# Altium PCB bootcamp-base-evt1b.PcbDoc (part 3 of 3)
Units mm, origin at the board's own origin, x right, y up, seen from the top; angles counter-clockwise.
Board outline 49.31 x 77.41 mm, 4 copper layers (Top Layer, Internal Plane 1, Internal Plane 2, Bottom Layer), stack 1.597 mm thick; 178 components, 122 nets, 1398 pads, 353 vias.
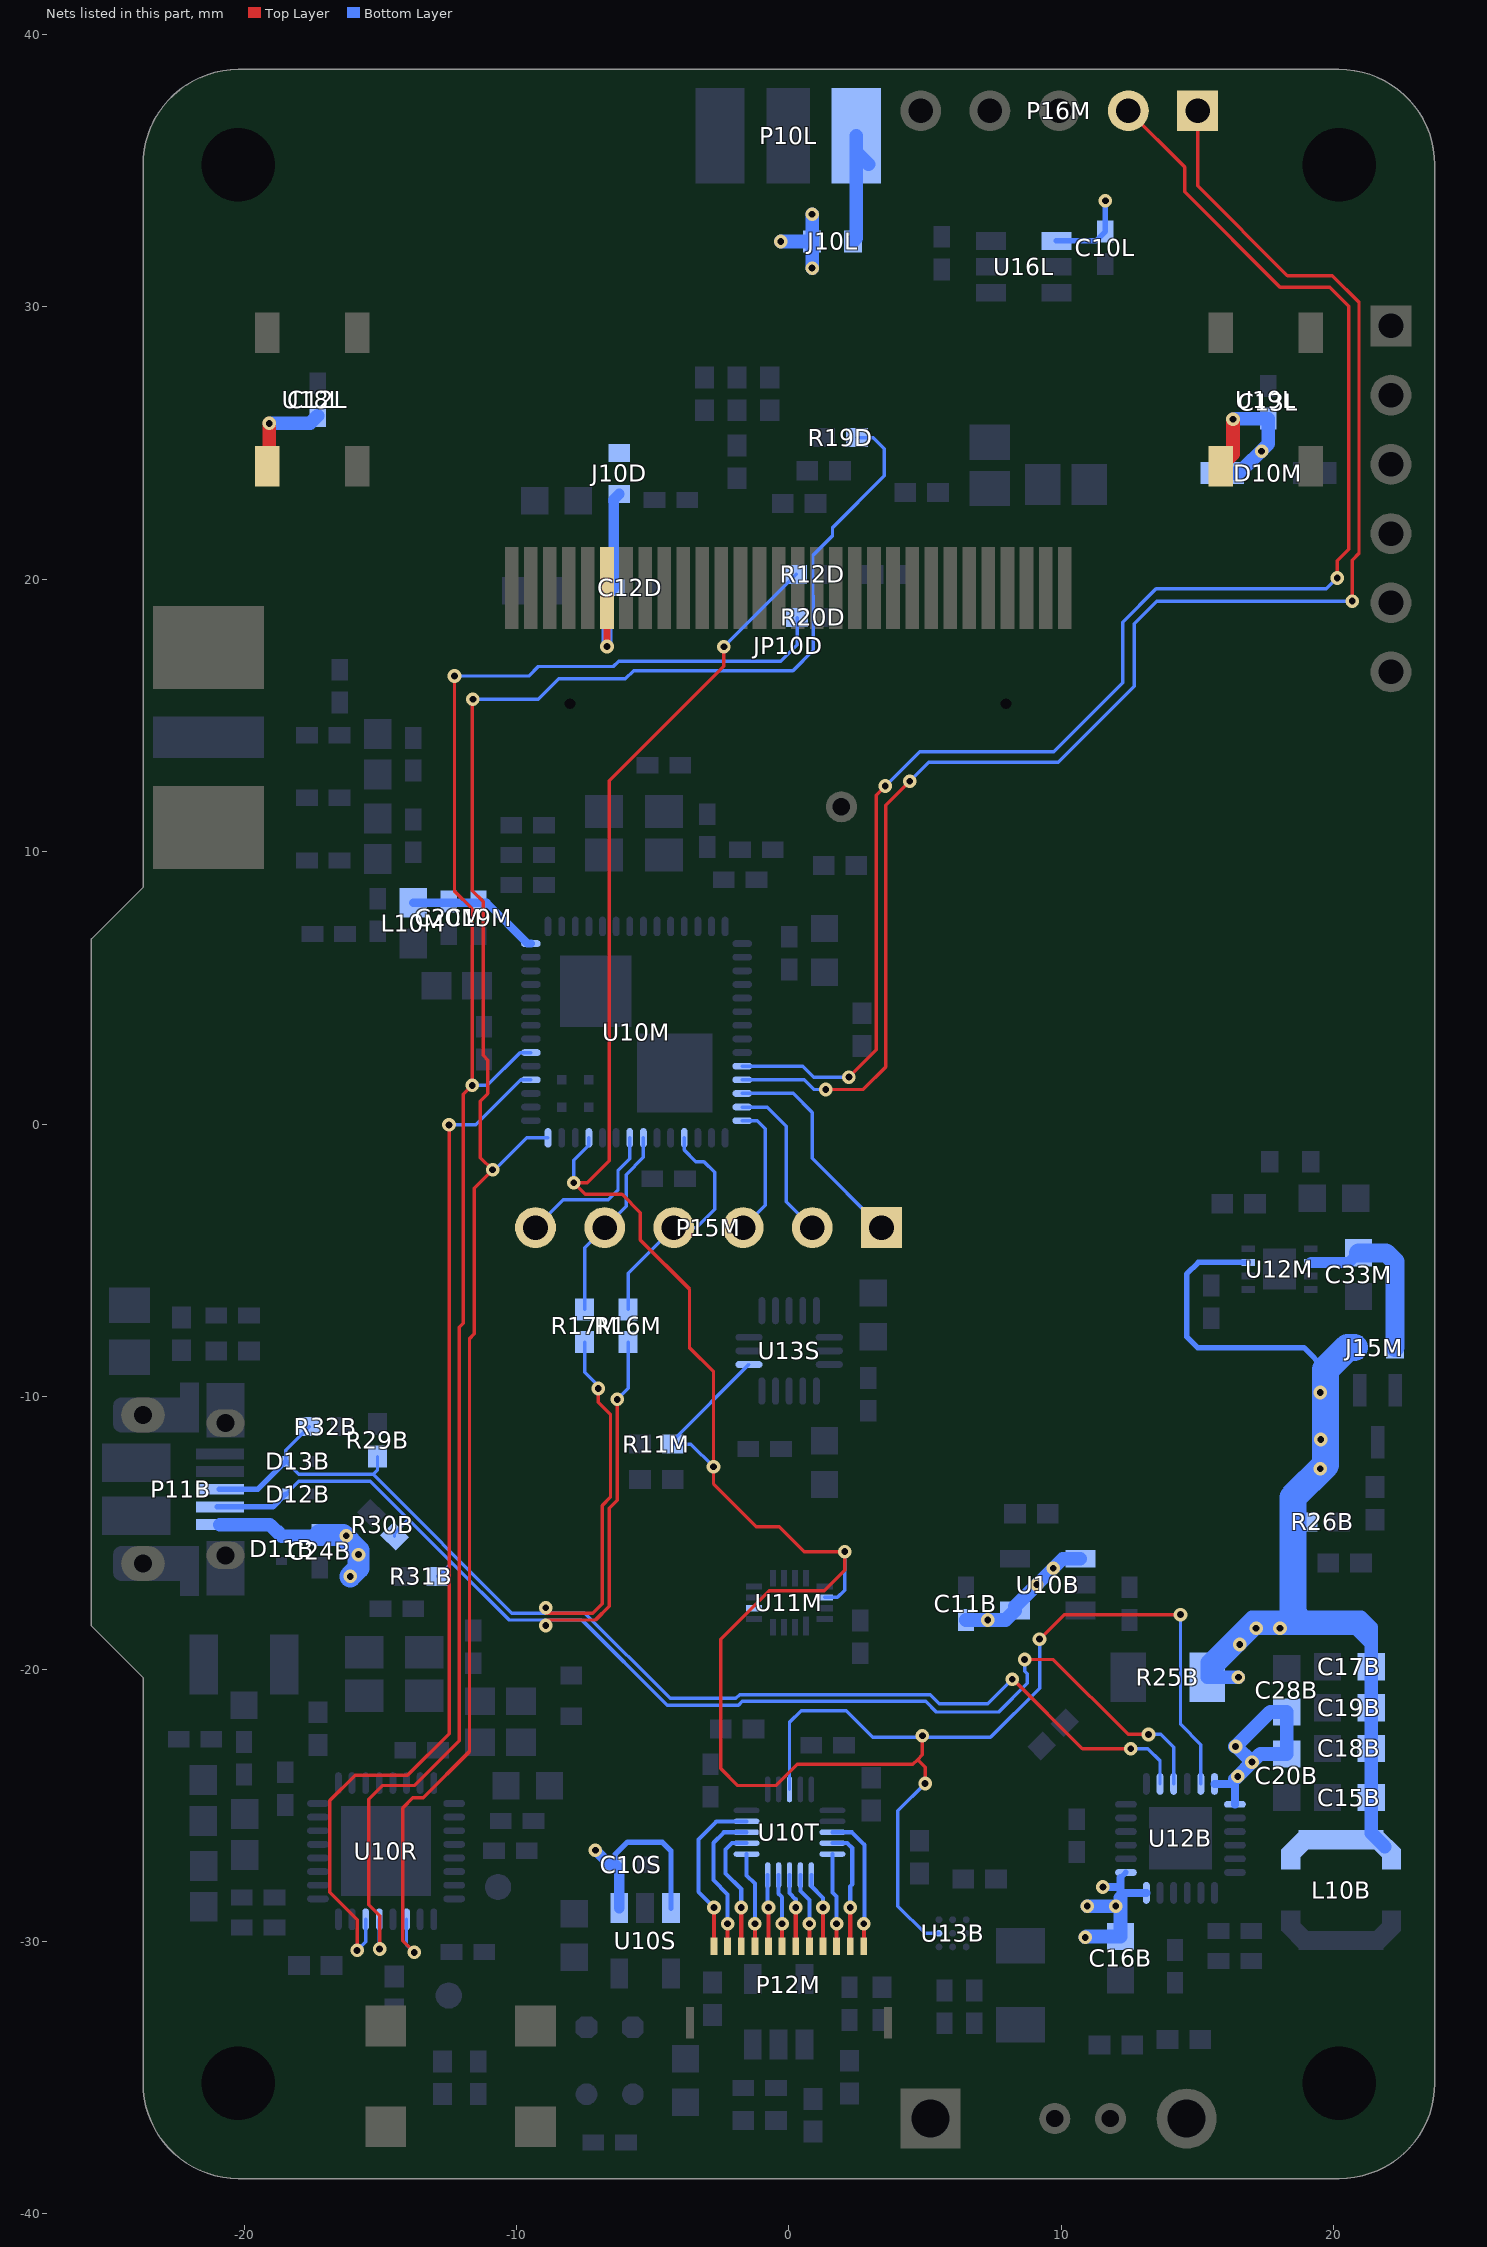
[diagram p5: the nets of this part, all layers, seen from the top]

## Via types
v1: diameter 0.5, hole 0.25, Top Layer to Bottom Layer, tented both sides, 320 vias
v2: diameter 0.5, hole 0.2, Top Layer to Bottom Layer, 18 vias
v3: diameter 0.66, hole 0.33, Top Layer to Bottom Layer, tented top, 13 vias
v4: diameter 0.5, hole 0.2, Top Layer to Bottom Layer, tented top, 2 vias

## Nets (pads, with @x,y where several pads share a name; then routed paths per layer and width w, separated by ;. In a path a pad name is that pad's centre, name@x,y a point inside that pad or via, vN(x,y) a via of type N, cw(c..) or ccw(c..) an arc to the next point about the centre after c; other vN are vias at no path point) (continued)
SDA: R11M.1 R12D.2 U10M.25 U10T.3 U11M.14 U12B.17 U13B.A2 U13S.6 | length 110.4
  Top Layer w0.125: v1(-2.388,17.525) -2.388,16.812 -6.6,12.6 -6.6,-1.35 -7.4,-2.15 v1(-7.9,-2.15) -7.475,-2.575 -6.125,-2.575 -5.45,-3.25 -5.45,-4.25 -3.65,-6.05 -3.65,-8.2 -2.767,-9.083 v1(-2.767,-12.571) -2.767,-13.208 -1.2,-14.775 -0.35,-14.775 0.563,-15.688 v1(2.05,-15.688) 2.05,-16.375 1.3,-17.125 -0.725,-17.125 -2.5,-18.9 -2.5,-23.65 -1.875,-24.275 -0.475,-24.275 0.3,-23.5 4.55,-23.5 4.725,-23.325 ; v1(4.9,-22.45) 4.9,-23.15 4.725,-23.325 ; v1(5,-24.2) 5,-23.6 4.725,-23.325 ; v1(9.2,-18.9) 10.1,-18 v1(14.375,-18)
  Bottom Layer w0.125: v1(-7.9,-2.15) -7.9,-1.325 -7.342,-0.767 U10M.25@-7.342,-0.501 ; v1(-2.767,-12.571) -3.597,-11.741 R11M.1@-4.263,-11.741 -4.263,-11.617 U13S.6@-1.467,-8.821 ; v1(-2.388,17.525) R12D.2@0.272,20.184 ; U10T.3@0.022,-24.416 0.022,-21.953 0.45,-21.525 2.1,-21.525 3.075,-22.5 7.4,-22.5 9.2,-20.7 v1(9.2,-18.9) ; U11M.14@1.321,-17.367 1.783,-17.367 2.05,-17.1 v1(2.05,-15.688) ; v1(5,-24.2) 4,-25.2 4,-28.7 5,-29.7 U13B.A2@5.508,-29.7 ; v1(14.375,-18) 14.375,-22.025 15.122,-22.772 U12B.17@15.122,-24.216
SPI1_MISO: U10M.32 U10R.14 | length 38.6
  Top Layer w0.125: v1(-15.85,-30.325) -15.85,-29.2 -16.85,-28.2 -16.85,-24.825 -15.925,-23.9 -14,-23.9 -12.475,-22.375 v1(-12.475,-0.025)
  Bottom Layer w0.125: v1(-15.85,-30.325) -15.536,-30.011 U10R.14@-15.536,-29.184 ; v1(-12.475,-0.025) -11.5,-0.025 -9.846,1.629 U10M.32@-9.472,1.629
SPI1_MOSI: R20D.2 U10M.34 U10R.13 | length 67.2
  Top Layer w0.125: v1(-15.025,-30.275) -15.025,-29.05 -15.425,-28.65 -15.425,-24.775 -14.925,-24.275 -13.75,-24.275 -12.1,-22.625 -12.1,-7.45 -11.95,-7.3 -11.95,1.1 v1(-11.625,1.425) -11.625,7.9 -12.275,8.55 v1(-12.275,16.45)
  Bottom Layer w0.125: U10R.13@-15.036,-29.184 -15.036,-30.264 v1(-15.025,-30.275) ; v1(-12.275,16.45) -9.55,16.45 -9.2,16.8 -6.45,16.8 -6.25,17 -0.3,17 0.3,17.6 R20D.2@0.3,18.6 ; v1(-11.625,1.425) -11.075,1.425 -9.871,2.629 U10M.34@-9.472,2.629
SPI1_SCK: R19D.2 U10M.28 U10R.11 | length 75.1
  Top Layer w0.125: v1(-13.75,-30.4) -14.175,-29.975 -14.175,-25.1 -13.8,-24.725 -13.425,-24.725 -11.725,-23.025 -11.725,-7.875 -11.55,-7.7 -11.55,-2.35 v1(-10.875,-1.675) -11.325,-1.225 -11.325,0.85 -11.05,1.125 -11.05,2.35 -11.225,2.525 -11.225,8.175 -11.625,8.575 -11.625,15.575 v1(-11.6,15.6)
  Bottom Layer w0.125: U10R.11@-14.036,-29.184 -14.036,-30.114 v1(-13.75,-30.4) ; v1(-11.6,15.6) -9.2,15.6 -8.45,16.35 -6,16.35 -5.7,16.65 0.15,16.65 0.9,17.4 0.9,19.4 0.884,19.416 0.884,20.884 1.6,21.6 1.6,21.9 3.5,23.8 3.5,24.8 3.1,25.2 R19D.2@2.5,25.2 ; v1(-10.875,-1.675) -10.8,-1.675 -9.626,-0.501 U10M.28@-8.842,-0.501
SWD_CLK_TOUCH1: P16M.2 U10M.10 | length 58.1
  Top Layer w0.125: v1(2.2,1.729) 3.2,2.729 3.2,12.075 v1(3.538,12.412) ; P16M.2@12.46,37.2 14.525,35.135 14.525,34.225 18.025,30.725 19.85,30.725 20.55,30.025 20.55,21.105 20.125,20.68 v1(20.125,20.05)
  Bottom Layer w0.125: U10M.10@-1.712,2.129 0.508,2.129 0.908,1.729 v1(2.2,1.729) ; v1(3.538,12.412) 4.8,13.675 9.725,13.675 12.25,16.2 12.25,18.425 13.475,19.65 19.725,19.65 v1(20.125,20.05)
SWD_DIO_TOUCH4: P16M.1 U10M.11 | length 58.5
  Top Layer w0.125: v1(1.35,1.275) 2.725,1.275 3.55,2.1 3.55,11.7 v1(4.438,12.588) ; P16M.1@15,37.2 15,34.45 18.3,31.15 19.95,31.15 20.925,30.175 20.925,20.95 20.675,20.7 v1(20.675,19.2)
  Bottom Layer w0.125: U10M.11@-1.712,1.629 0.558,1.629 0.912,1.275 v1(1.35,1.275) ; v1(4.438,12.588) 5.136,13.286 9.886,13.286 12.675,16.075 12.675,18.375 13.5,19.2 v1(20.675,19.2)
TOUCH2: P15M.3 U10M.14 | length 4.9
  Bottom Layer w0.125: U10M.14@-1.712,0.129 -1.167,0.129 -0.867,-0.171 -0.867,-2.981 P15M.3@-1.682,-3.796
TOUCH3: P15M.2 U10M.13 | length 6
  Bottom Layer w0.125: U10M.13@-1.712,0.629 -0.792,0.629 -0.092,-0.071 -0.092,-2.846 P15M.2@0.858,-3.796
TOUCH5: P15M.1 U10M.12 | length 8.1
  Bottom Layer w0.125: U10M.12@-1.712,1.129 0.158,1.129 0.858,0.429 0.858,-1.256 P15M.1@3.398,-3.796
TOUCH6: P15M.4 R16M.2 U10M.18 | length 8.7
  Bottom Layer w0.125: R16M.2@-5.9,-6.8 -5.9,-5.475 P15M.4@-4.222,-3.796 -3.396,-3.796 -2.725,-3.125 -2.725,-1.763 -3.117,-1.371 -3.417,-1.371 -3.842,-0.946 U10M.18@-3.842,-0.501
TOUCH7: P15M.5 R17M.2 U10M.21 | length 7.2
  Bottom Layer w0.125: R17M.2@-7.5,-6.8 -7.5,-4.535 P15M.5@-6.762,-3.796 -5.975,-3.01 -5.975,-1.855 -5.342,-1.221 U10M.21@-5.342,-0.501
TOUCH8: P15M.6 U10M.22 | length 5.7
  Bottom Layer w0.125: P15M.6@-9.302,-3.796 -8.28,-2.775 -6.625,-2.775 -6.275,-2.425 -6.275,-1.705 -5.842,-1.271 U10M.22@-5.842,-0.501
TPAD0: P12M.1 U10T.19 | length 6.2
  Top Layer w0.15: P12M.1@-2.75,-30.175 v1(-2.75,-28.75)
  Bottom Layer w0.15: v1(-2.75,-28.75) -3.325,-28.175 -3.325,-26.25 -2.666,-25.591 U10T.19@-1.553,-25.591
TPAD1: P12M.2 U10T.18 | length 5.4
  Top Layer w0.15: P12M.2@-2.25,-30.175 v1(-2.25,-29.35)
  Bottom Layer w0.15: v1(-2.25,-29.35) -2.25,-28.275 -2.775,-27.75 -2.775,-26.375 -2.391,-25.991 U10T.18@-1.553,-25.991
TPAD2: P12M.3 U10T.17 | length 4.7
  Top Layer w0.15: P12M.3@-1.75,-30.175 v1(-1.75,-28.75)
  Bottom Layer w0.15: v1(-1.75,-28.75) -1.75,-28.075 -2.325,-27.5 -2.325,-26.625 -2.091,-26.391 U10T.17@-1.553,-26.391
TPAD3: P12M.4 U10T.16 | length 3.5
  Top Layer w0.15: P12M.4@-1.25,-30.175 v1(-1.25,-29.35)
  Bottom Layer w0.15: U10T.16@-1.553,-26.791 -1.553,-27.572 -1.25,-27.875 v1(-1.25,-29.35)
TPAD4: P12M.5 U10T.15 | length 2.6
  Top Layer w0.15: P12M.5@-0.75,-30.175 v1(-0.75,-28.75)
  Bottom Layer w0.15: U10T.15@-0.778,-27.566 -0.778,-28.722 v1(-0.75,-28.75)
TPAD5: P12M.6 U10T.14 | length 2.7
  Top Layer w0.15: P12M.6@-0.25,-30.175 v1(-0.25,-29.35)
  Bottom Layer w0.15: U10T.14@-0.378,-27.566 -0.378,-28.247 -0.25,-28.375 v1(-0.25,-29.35)
TPAD6: P12M.7 U10T.13 | length 2.7
  Top Layer w0.15: P12M.7@0.25,-30.175 v1(0.25,-28.75)
  Bottom Layer w0.15: U10T.13@0.022,-27.566 0.022,-28.222 0.25,-28.45 v1(0.25,-28.75)
TPAD7: P12M.8 U10T.12 | length 2.7
  Top Layer w0.15: P12M.8@0.75,-30.175 v1(0.75,-29.35)
  Bottom Layer w0.15: U10T.12@0.422,-27.566 0.422,-28.147 0.75,-28.475 v1(0.75,-29.35)
TPAD8: P12M.9 U10T.11 | length 2.8
  Top Layer w0.15: P12M.9@1.25,-30.175 v1(1.25,-28.75)
  Bottom Layer w0.15: U10T.11@0.822,-27.566 0.822,-27.972 1.25,-28.4 v1(1.25,-28.75)
TPADA: P12M.12 U10T.8 | length 5.1
  Top Layer w0.15: P12M.12@2.75,-30.175 v1(2.75,-29.35)
  Bottom Layer w0.15: U10T.8@1.597,-25.991 2.316,-25.991 2.775,-26.45 2.775,-29.325 v1(2.75,-29.35)
TPADB: P12M.11 U10T.9 | length 4.4
  Top Layer w0.15: P12M.11@2.25,-30.175 v1(2.25,-28.75)
  Bottom Layer w0.15: U10T.9@1.597,-26.391 2.141,-26.391 2.325,-26.575 2.325,-27.9 2.25,-27.975 v1(2.25,-28.75)
TPADC: P12M.10 U10T.10 | length 3.4
  Top Layer w0.15: P12M.10@1.75,-30.175 v1(1.75,-29.35)
  Bottom Layer w0.15: U10T.10@1.597,-26.791 1.597,-28.197 1.75,-28.35 v1(1.75,-29.35)
USBD_N: D12B.1 P11B.2 R16M.1 R30B.1 R31B.1 U12B.15 | length 57.3
  Top Layer w0.125: v1@-8.9,-18.2 -7.1,-18.2 -6.6,-17.7 -6.6,-14.1 -6.3,-13.8 v1(-6.3,-10.1) ; v1(8.65,-19.65) 9.7,-19.65 12.45,-22.4 v1(13.2,-22.4)
  Bottom Layer w0.125: D12B.1@-18.473,-13.579 -17.998,-13.104 -15.366,-13.104 -13.97,-14.5 ; R30B.1@-14.476,-15.124 -14.476,-15.006 -13.97,-14.5 ; R31B.1@-12.9,-16.6 -12.87,-16.6 -12.37,-16.1 ; v1(-6.3,-10.1) -5.9,-9.7 R16M.1@-5.9,-8 ; v1(8.65,-19.65) 8.65,-20.075 8.75,-20.175 8.75,-20.525 7.7,-21.575 5.414,-21.575 5.025,-21.186 -1.707,-21.186 -1.85,-21.329 -4.466,-21.329 -7.595,-18.2 -10.27,-18.2 -12.37,-16.1 ; v1(13.2,-22.4) 13.65,-22.4 14.122,-22.872 U12B.15@14.122,-24.216 ; -13.97,-14.5 -12.37,-16.1
  Bottom Layer w0.2: P11B.2@-20.989,-14.044 -18.938,-14.044 D12B.1@-18.473,-13.579
  other v1: -8.925,-18.4
USBD_P: D13B.1 P11B.3 R17M.1 R29B.1 R32B.1 U12B.14 | length 55.9
  Top Layer w0.125: v1@-8.9,-17.95 -7.204,-17.95 -6.85,-17.596 -6.85,-13.996 -6.55,-13.696 -6.55,-10.65 -7,-10.2 v1(-7,-9.7) ; v1(8.2,-20.375) 8.225,-20.375 10.775,-22.925 v1(12.55,-22.925)
  Bottom Layer w0.125: R32B.1@-17.6,-11.1 -18.473,-11.973 D13B.1@-18.473,-12.379 -17.998,-12.854 -15.263,-12.854 ; R29B.1@-15.1,-12.2 -15.1,-12.691 -15.263,-12.854 ; R17M.1@-7.5,-8 -7.5,-9.1 -7,-9.6 v1(-7,-9.7) ; v1(8.2,-20.375) 7.3,-21.275 5.525,-21.275 5.186,-20.936 -1.811,-20.936 -1.954,-21.079 -4.363,-21.079 -7.492,-17.95 -10.167,-17.95 -15.263,-12.854 ; v1(12.55,-22.925) 13.175,-22.925 13.622,-23.372 U12B.14@13.622,-24.216
  Bottom Layer w0.2: P11B.3@-20.916,-13.398 -19.492,-13.398 D13B.1@-18.473,-12.379
  other v1: -8.925,-17.75
USBOUT_EN_N: U11M.6
VBAT_SYS: C10S.1 C12D.1 C15B.1 C16B.1 C17B.1 C18B.1 C19B.1 C33M.1 J10D.1 J15M.1 JP10D.6 L10B.2 R25B.2 R26B.2 U10S.1 U10S.3 U12B.6 U12B.7 U12M.2 U12M.7 | length 73.7
  Top Layer w0.25: v1(-6.678,17.534) JP10D.6@-6.678,19.684
  Bottom Layer w0.2: C10S.1@-6.379,-27.177 -6.379,-26.804 -5.925,-26.35 -4.65,-26.35 -4.329,-26.671 U10S.3@-4.329,-28.777 ; 12.172,-28.391 12.347,-28.216 ; 12.172,-27.666 U12B.7@12.372,-27.466 ; U12M.7@16.858,-5.071 15.029,-5.071 14.6,-5.5 14.6,-7.8 15,-8.2 18.9,-8.2 19.7,-9
  Bottom Layer w0.3: v1(11.525,-28) 12.172,-28 ; 12.172,-28.391 12.172,-28 ; 12.172,-27.666 12.172,-28 ; 12.347,-28.216 U12B.6@13.122,-28.216
  Bottom Layer w0.4: v1(-7.104,-26.652) -6.579,-27.177 C10S.1@-6.379,-27.177 -6.229,-27.327 U10S.1@-6.229,-28.777 ; v1(-6.678,17.534) -6.678,19.434 C12D.1@-6.428,19.684 -6.428,22.934 J10D.1@-6.228,23.134 ; U12M.2@19.158,-5.071 20.558,-5.071 C33M.1@20.908,-4.721
  Bottom Layer w0.5: v1(10.875,-29.85) 10.909,-29.816 C16B.1@12.172,-29.816 v1@12.172,-28.7 ; v1(10.95,-28.7) v1@12.172,-28.7 ; 12.172,-28.391 v1@12.172,-28.7 ; v1(16.5,-20.3) R25B.2@15.35,-20.3 ; L10B.2@21.872,-26.516 21.372,-26.016 C15B.1@21.372,-24.716 C18B.1@21.372,-22.916 C19B.1@21.372,-21.416 C17B.1@21.372,-19.916 21.372,-19.066 ; R25B.2@15.35,-20.3 15.35,-19.75 17,-18.1 18.6,-18.1 21,-18.1 21.372,-18.472 21.372,-19.066 ; R25B.2@15.35,-20.3 v1(17.15,-18.5) v1(18.025,-18.5) 20.806,-18.5 21.372,-19.066
  Bottom Layer w0.7: C33M.1@20.908,-4.721 21.921,-4.721 22.25,-5.05 J15M.1@22.25,-8.2
  Bottom Layer w1: 18.6,-18.1 18.5,-18 18.5,-13.7 19.7,-12.5 19.7,-9 20.5,-8.2 J15M.1@20.75,-8.2
  other v1: 12,-28.7 16.55,-19.1 19.5,-12.65 19.525,-11.575 19.5,-9.85
VR_PA: C19M.1 C20M.1 L10M.1 U10M.42 | length 4.9
  Bottom Layer w0.3: L10M.1@-13.792,8.129 -11.092,8.129 -9.592,6.629 U10M.42@-9.472,6.629
VUSB: C10L.1 C11B.1 C12L.1 C13L.1 C20B.1 C24B.1 C28B.1 D10M.2 D11B.1 J10L.1 P10L.3 P11B.1 U10B.1 U10B.4 U12B.18 U12B.19 U16L.1 U18L.1 U19L.1 | length 41.4
  Top Layer w0.5: U18L.1@-19.15,24.15 -19.075,24.225 v1(-19.075,25.725) ; U19L.1@15.85,24.15 16.3,24.6 v1(16.3,25.875)
  Bottom Layer w0.2: U16L.1@9.816,32.422 11.266,32.422 C10L.1@11.616,32.772 v1(11.616,33.897) ; 16.197,-24.216 v1@16.372,-24.041
  Bottom Layer w0.3: U12B.18@15.622,-24.216 16.197,-24.216 ; U12B.19@16.372,-24.966 v1@16.372,-24.041
  Bottom Layer w0.5: P11B.1@-20.882,-14.7 -19.051,-14.7 D11B.1@-18.623,-15.129 ; v1(-19.075,25.725) -17.575,25.725 C12L.1@-17.3,26 ; -18.748,-14.954 D11B.1@-18.623,-15.129 ; C24B.1@-17.223,-15.079 -17.273,-15.129 D11B.1@-18.623,-15.129 ; v1(-0.3,32.4) J10L.1@0.85,32.4 ; v1(0.85,31.425) J10L.1@0.85,32.4 ; v1(0.85,33.4) J10L.1@0.85,32.4 ; J10L.1@2.35,32.4 2.472,32.522 P10L.3@2.472,35.684 ; P10L.3@2.472,36.284 P10L.3@2.472,35.684 ; P10L.3@2.922,35.234 P10L.3@2.472,35.684 ; C11B.1@6.5,-18.2 7.95,-18.2 U10B.4@8.3,-17.85 8.3,-17.7 10.05,-15.95 U10B.1@10.7,-15.95 ; D10M.2@15.9,23.9 16.525,23.9 17.6,24.975 C13L.1@17.6,25.9 16.325,25.9 v1(16.3,25.875) ; v1@16.372,-24.041 v1(16.472,-23.941) v1(16.997,-23.416) ; v1@16.372,-22.841 v1(16.397,-22.841) ; v1(16.397,-22.841) 16.422,-22.841 v1(16.997,-23.416) ; v1(16.397,-22.841) 17.662,-21.575 C28B.1@18.275,-21.575 18.272,-21.578 C20B.1@18.272,-23.116 17.297,-23.116 v1(16.997,-23.416)
  Bottom Layer w0.8: C24B.1@-17.223,-15.079 -16.367,-15.079 -15.8,-15.645 -15.8,-16.3 v1(-16.1,-16.6)
  other v1: 7.3,-18.2 9.1,-16.9 9.7,-16.3 -15.8,-15.8 -16.248,-15.104 17.35,24.7
pads on no net: JP10D.0 JP10D.7 P11B.4 P11M.2 P11M.6 P12M.0 U10M.30 U10M.37 U10M.41 U10M.50 U10M.51 U10M.52 U10M.53 U10M.57 U10M.58 U10M.59 U10M.60 U10R.4 U10R.5 U10R.6 U10R.15 U10S.4 U12B.11 U12M.5 U13S.3 U13S.8 U13S.9 U13S.13 U13S.15 U13S.16

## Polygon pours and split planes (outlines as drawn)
GND on Bottom Layer "bot-gnd" (solid, remove dead copper, pour order 6): -31.5,-42.65 25.95,-42.65 29.325,-39.275 29.325,37.175 24.45,42.05 -25.225,42.05 -29.8,37.475 -30.4,36.875 -30.4,-42.875
GND on Top Layer "top-gnd" (solid, remove dead copper, pour order 4): -32,-40.9 23.475,-40.9 29.175,-35.2 29.175,37.9 25.025,42.05 -27.95,42.05 -33.7,36.3 -33.7,-39.15 -31.95,-40.9
VBAT_SYS on Internal Plane 1 (split plane): 170 vertices, not listed, extent -7.473,-32.898 20.398,23.556
VUSB on Internal Plane 1 (split plane): 234 vertices, not listed, extent -25.09,-38.192 23.198,38.206
P3.0V on Internal Plane 1 (split plane): 10.028,30.728 10.061,30.706 10.1,30.698 11.758,30.698 13.398,29.058 13.398,24.5 13.406,24.461 13.428,24.428 14.156,23.7 10.858,20.402 -5.8,20.402 -5.839,20.394 -5.872,20.372 -7.572,18.672 -7.594,18.639 -7.602,18.6 -7.602,17 -7.594,16.961 -7.572,16.928 -7.272,16.628 -7.239,16.606 -7.2,16.598 -6.4,16.598 -6.361,16.606 -6.328,16.628 -4.158,18.798 11.4,18.798 11.439,18.806 11.472,18.828 13.442,20.798 16.033,20.798 18.098,18.733 18.098,-2.4 18.106,-2.439 18.128,-2.472 18.598,-2.942 18.598,-7.758 17.828,-8.528 17.806,-8.561 17.798,-8.6 17.798,-11.958 16.158,-13.598 13.542,-13.598 12.372,-12.428 12.339,-12.406 12.3,-12.398 6.1,-12.398 6.061,-12.406 6.028,-12.428 3.728,-14.728 3.706,-14.761 3.698,-14.8 3.698,-20.5 3.706,-20.539 3.728,-20.572 5.528,-22.372 5.561,-22.394 5.6,-22.402 8,-22.402 8.039,-22.394 8.072,-22.372 9.942,-20.502 10.258,-20.502 10.598,-20.842 10.598,-23.358 9.658,-24.298 9.1,-24.298 9.061,-24.306 9.028,-24.328 6.728,-26.628 4.528,-28.828 2.558,-30.798 -2.333,-30.798 -3.398,-29.733 -3.398,-28.325 -3.406,-28.286 -3.428,-28.253 -3.753,-27.928 -3.786,-27.906 -3.825,-27.898 -4.358,-27.898 -6.328,-25.928 -6.361,-25.906 -6.4,-25.898 -7.175,-25.898 -7.214,-25.906 -7.247,-25.928 -7.647,-26.328 -7.669,-26.361 -7.677,-26.4 -7.677,-27 -7.669,-27.039 -7.647,-27.072 -7.102,-27.617 -7.102,-31.798 -16.858,-31.798 -19.898,-28.758 -19.898,-27.842 -19.428,-27.372 -19.406,-27.339 -19.398,-27.3 -19.398,-20.442 -16.458,-17.502 -15.8,-17.502 -15.761,-17.494 -15.728,-17.472 -15.028,-16.772 -15.006,-16.739 -14.998,-16.7 -14.998,-15.4 -15.006,-15.361 -15.028,-15.328 -16.003,-14.353 -16.036,-14.331 -16.075,-14.323 -25.09,-14.323 -25.09,6.589 -23.346,8.332 -23.283,8.409 -23.236,8.498 -23.206,8.593 -23.197,8.693 -23.197,22.498 -15,22.498 -14.961,22.506 -14.928,22.528 -14.128,23.328 -14.106,23.361 -14.098,23.4 -14.098,29.658 -13.008,30.748 1.85,30.748 1.889,30.756 1.922,30.778 4.342,33.198 7.558,33.198
GND on Internal Plane 2 (split plane): 20.442,38.197 20.675,38.169 20.906,38.123 21.132,38.06 21.352,37.978 21.565,37.88 21.77,37.765 21.966,37.635 22.15,37.489 22.323,37.33 22.482,37.157 22.628,36.973 22.758,36.778 22.873,36.573 22.971,36.359 23.053,36.139 23.116,35.913 23.162,35.682 23.19,35.449 23.198,35.23 23.197,35.214 23.197,-35.186 23.197,-35.187 23.197,-35.201 23.198,-35.217 23.19,-35.435 23.162,-35.668 23.116,-35.898 23.053,-36.125 22.971,-36.345 22.873,-36.558 22.758,-36.763 22.628,-36.959 22.482,-37.143 22.323,-37.316 22.15,-37.475 21.966,-37.621 21.77,-37.751 21.565,-37.866 21.352,-37.964 21.132,-38.046 20.906,-38.109 20.675,-38.155 20.442,-38.183 20.214,-38.192 20.194,-38.19 -20.207,-38.19 -20.223,-38.191 -20.442,-38.183 -20.675,-38.155 -20.906,-38.109 -21.132,-38.045 -21.352,-37.964 -21.565,-37.866 -21.77,-37.751 -21.966,-37.621 -22.15,-37.475 -22.323,-37.316 -22.482,-37.143 -22.628,-36.959 -22.758,-36.763 -22.873,-36.558 -22.971,-36.345 -23.053,-36.125 -23.116,-35.898 -23.162,-35.668 -23.19,-35.435 -23.198,-35.217 -23.197,-35.2 -23.197,-20.31 -23.206,-20.21 -23.236,-20.115 -23.283,-20.026 -23.346,-19.949 -25.09,-18.206 -25.09,6.589 -23.346,8.332 -23.283,8.409 -23.236,8.498 -23.206,8.593 -23.197,8.693 -23.197,35.2 -23.199,35.22 -23.19,35.449 -23.162,35.682 -23.116,35.913 -23.052,36.139 -22.971,36.359 -22.873,36.572 -22.758,36.777 -22.628,36.973 -22.482,37.157 -22.323,37.33 -22.15,37.489 -21.966,37.635 -21.77,37.765 -21.565,37.88 -21.352,37.978 -21.132,38.06 -20.906,38.123 -20.675,38.169 -20.442,38.197 -20.223,38.205 -20.207,38.204 20.179,38.204 20.199,38.206 20.207,38.206

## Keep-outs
Keep-Out Layer:
  lines w0.2: -23.707,8.693 -23.707,22.3
  lines w0.5: -25.6,-18.417 -25.6,6.8 -23.707,8.693
  lines w1: -25.6,-18.417 -23.707,-20.31 -23.707,-35.2 ccw(c-20.207,-35.2) -20.207,-38.7 20.194,-38.7 ccw(c20.207,-35.2) 23.707,-35.2 ; -23.707,22.3 -23.707,35.2 cw(c-20.207,35.214) -20.207,38.714 20.179,38.714 cw(c20.207,35.214) 23.707,35.214 23.707,-35.186

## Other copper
Top Layer:
  pour cut-out: -15.5,37.7 -15.5,36 -10.4,36 -10.4,37.7
  text "1" at -15.2,36.7 h0.7
Bottom Layer:
  pour cut-out: -15.507,36 -15.507,37.7 -10.407,37.7 -10.407,36
  text "4" at -11.307,36.7 h0.7
Internal Plane 1 (plane layer: these items are gaps in the copper):
  rectangle: -15.507,36.3 -14.707,37.7
  rectangle: -13.807,36.3 -10.407,37.7
  region: 19.608,-7.596 19.608,-3.296 18.658,-3.296 18.658,-7.596
  lines w0.2: -25.5,-14.425 -16.075,-14.425 -15.1,-15.4 -15.1,-16.7 -15.8,-17.4 -16.5,-17.4 -19.5,-20.4 -19.5,-27.3 -20,-27.8 -20,-28.8 -16.9,-31.9 -4.025,-31.9 -2.925,-33 4.1,-33 6.95,-30.15 7.975,-30.15 8.125,-30 8.775,-30 9.45,-30.675 11.425,-30.675 13.725,-28.375 15.375,-28.375 16.55,-27.2 16.55,-25.075 15.775,-24.3 15.1,-23.625 15.1,-22 10.9,-17.8 8.7,-17.8 7.7,-18.8 6.8,-18.8 6.4,-18.4 6.4,-17.6 8.8,-15.2 10.1,-15.2 10.9,-16 11.7,-16 14.375,-16 15.4,-17.025 15.4,-20.1 16.4,-21.1 17.075,-21.1 18.975,-19.2 18.975,-17.85 18.5,-17.375 18.5,-15.875 20,-14.375 20,-9.1 20.5,-8.6 20.5,-2.3 19.6,-1.4 19.6,20.8 18,22.4 15.6,22.4 13.5,24.5 13.5,29.1 11.8,30.8 10.1,30.8 7.6,33.3 4.3,33.3 1.85,30.85 -13.05,30.85 -14.2,29.7 -14.2,23.4 -15,22.6 -23.607,22.6 ; -7,-31.9 -7,-27.575 -7.575,-27 -7.575,-26.4 -7.175,-26 -6.6,-26 -6.4,-26 -4.4,-28 -3.825,-28 -3.5,-28.325 -3.5,-29.775 -2.375,-30.9 2.6,-30.9 4.6,-28.9 6.8,-26.7 9.1,-24.4 9.7,-24.4 10.7,-23.4 10.7,-20.8 10.3,-20.4 9.9,-20.4 8,-22.3 5.6,-22.3 3.8,-20.5 3.8,-14.8 6.1,-12.5 12.3,-12.5 13.5,-13.7 16.2,-13.7 17.9,-12 17.9,-8.6 18.7,-7.8 18.7,-2.9 18.2,-2.4 18.2,18.775 16.075,20.9 13.4,20.9 11.4,18.9 -4.2,18.9 -6.4,16.7 -7.2,16.7 -7.5,17 -7.5,18.6 -5.8,20.3 10.9,20.3 14.3,23.7
  text "2" at -14.507,36.7 h0.7
Internal Plane 2 (plane layer: these items are gaps in the copper):
  rectangle: -15.507,36.1 -12.307,37.7
  rectangle: -11.507,36 -10.407,37.7
  text "3" at -12.107,36.7 h0.7

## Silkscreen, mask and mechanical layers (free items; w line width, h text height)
Top Overlay:
  rectangle: 18.2,1.4 22.2,14.7
  rectangle: 5.3,-21.4 9.3,-20.4
  rectangle: 8.3,-24.4 9.3,-20.4
  rectangle: 8.3,-24.4 12.3,-23.4
  rectangle: 11.3,-27.4 12.3,-23.4
  rectangle: 5.3,-27.4 9.3,-26.4
  rectangle: 5.3,-27.4 6.3,-23.4
  lines w0.2: -14.551,-26.319 ccw(c-13.683,-26.319) -13.683,-27.186 -6.423,-27.186 ccw(c-6.423,-26.17) -5.407,-26.17 -5.407,-21.598 ccw(c-6.423,-21.598) -6.423,-20.582 -13.535,-20.582 ccw(c-13.535,-21.598) -14.551,-21.598 -14.551,-26.319
  text "SWD" at 14.1,34.8 h0.75
  text "UART" at 19.8,30.9 h0.75
  text "SN:" at 21.8,-0.9 h0.75 r90
  text "RESET" at -7.9,-33.4 h0.75 r270
  text "BAT+" at 4.075,-35.1 h0.75
  text "T+" at 9.3,-35.1 h0.75
  text "T-" at 11.5,-35.1 h0.75
  text "BAT-" at 13.6,-35.1 h0.75
Bottom Overlay:
  circle w0.127: c20.741,13.605 r0.583
  circle w0.2: c6.088,-7.612 r0.6
  lines w0.2: -0.3,33.775 0,34.075 ; 0,33.175 0,34.075 ; 0.3,33.775 0,34.075 ; 5.663,-8.037 6.488,-7.212 ; 5.688,-7.187 6.513,-8.012 ; 5.713,-11.337 6.113,-11.737 ; 5.813,-12.662 5.313,-12.162 6.513,-12.162 6.713,-12.162 7.213,-12.662 ; 6.013,-12.162 6.513,-12.662 ; 6.113,-8.737 6.113,-11.737 ; 6.513,-11.338 6.113,-11.737 ; 7.188,-7.612 10.188,-7.612 ; 9.788,-8.012 10.188,-7.612 ; 9.788,-7.212 10.188,-7.612 ; 10.588,-7.712 11.088,-7.212 ; 11.088,-7.912 10.588,-8.412 10.588,-7.212 10.587,-7.012 11.087,-6.512 ; 6.113,-11.737 6.113,-11.737
  text "RES" at 5.8,34.7 h0.75
  text "GND" at 8.4,34.7 h0.75
  text "3V" at 10.6,34.7 h0.75
  text "SWC" at 13.4,34.7 h0.75
  text "SWD" at 16,34.7 h0.75
  text "Orchard Bootcamp" at -4.975,33.675 h0.75
  text "GND" at -1.6,33.25 h0.75
  text "+5" at 3.2,33.25 h0.75
  text "Designed in" at -4.906,32.219 h0.76
  text "Singapore" at -4.906,30.819 h0.76
  text "GND" at 20.4,30.2 h0.75 r90
  text "EVT1b" at -9.4,29.325 h0.75
  text "04/15" at -4.925,29.325 h0.76
  text "+V" at 20.6,24.8 h0.75
  text "RX" at 20.4,22.4 h0.75 r90
  text "TX" at 20.4,19.7 h0.75 r90
  text "CERN OHL v1.2" at 22.5,14.2 h0.76 r90
  text "c bunnie@kosagi.com" at 20.991,13.872 h0.76 r90
  text "DAC0" at 3.1,12.475 h0.75
  text "Z=1g" at 6.288,-4.412 h0.6 r90
  text "X=0g" at 8.088,-4.712 h0.6 r90
  text "Y=1g" at 9.287,-4.712 h0.6 r90
  text "X=-1g" at 9.437,-9.487 h0.6
  text "Y=0g" at 9.437,-10.687 h0.6
  text "+" at 4.9,-35.3 h0.75
  text "-" at 14.3,-35.3 h0.75
  text "T" at 9.95,-35.6 h0.7
Top Solder:
  region: -10.407,36 -10.407,37.7 -15.507,37.7 -15.507,36
Bottom Solder:
  region: -10.407,36 -10.407,37.7 -15.507,37.7 -15.507,36
Mechanical 3:
  lines w0.127: 69.449,-41.957 70.719,-43.227 ; 69.449,12.653 70.719,13.923 ; 71.989,-41.957 70.719,-43.227 ; 71.989,12.653 70.719,13.923 ; 94.849,-39.417 136.759,-39.417 ; 94.849,-26.177 136.759,-26.177 134.219,-28.717 ; 94.849,-0.587 136.759,-0.587 134.219,-3.127 ; 94.849,10.113 136.759,10.113 ; 96.119,-28.717 98.659,-26.177 ; 96.119,-3.127 98.659,-0.587 ; 97.389,-38.147 98.659,-39.417 ; 97.389,-28.717 99.929,-26.177 ; 97.389,-26.177 94.849,-28.717 136.759,-28.717 ; 97.389,-3.127 99.929,-0.587 ; 97.389,-0.587 94.849,-3.127 136.759,-3.127 ; 97.389,8.843 98.659,10.113 ; 98.659,-28.717 101.199,-26.177 ; 98.659,-3.127 101.199,-0.587 ; 99.929,-38.147 98.659,-39.417 ; 99.929,8.843 98.659,10.113 ; 101.199,-28.717 103.739,-26.177 ; 101.199,-3.127 103.739,-0.587 ; 102.469,-28.717 105.009,-26.177 ; 102.469,-3.127 105.009,-0.587 ; 103.739,-28.717 106.279,-26.177 ; 103.739,-3.127 106.279,-0.587 ; 106.279,-28.717 108.819,-26.177 ; 106.279,-3.127 108.819,-0.587 ; 107.549,-28.717 110.089,-26.177 ; 107.549,-3.127 110.089,-0.587 ; 108.819,-28.717 111.359,-26.177 ; 108.819,-3.127 111.359,-0.587 ; 110.089,-28.717 112.629,-26.177 ; 110.089,-3.127 112.629,-0.587 ; 112.629,-28.717 115.169,-26.177 ; 112.629,-3.127 115.169,-0.587 ; 113.899,-28.717 116.439,-26.177 ; 113.899,-3.127 116.439,-0.587 ; 115.169,-28.717 117.709,-26.177 ; 115.169,-3.127 117.709,-0.587 ; 116.439,-28.717 118.979,-26.177 ; 116.439,-3.127 118.979,-0.587 ; 118.979,-28.717 121.519,-26.177 ; 118.979,-3.127 121.519,-0.587 ; 120.249,-28.717 122.789,-26.177 ; 120.249,-3.127 122.789,-0.587 ; 124.059,-28.717 126.599,-26.177 ; 124.059,-3.127 126.599,-0.587 ; 125.329,-28.717 127.869,-26.177 ; 125.329,-3.127 127.869,-0.587 ; 127.851,11.436 129.121,12.706 ; 127.876,-40.809 129.146,-39.539 ; 127.876,-39.539 127.876,-42.079 ; 129.121,10.166 131.661,12.706 ; 129.139,-28.717 131.679,-26.177 ; 129.139,-3.127 131.679,-0.587 ; 129.146,-42.079 131.686,-39.539 131.686,-42.079 127.876,-42.079 ; 130.391,12.706 127.851,10.166 127.851,12.706 131.661,12.706 ; 130.409,-28.717 132.949,-26.177 ; 130.409,-3.127 132.949,-0.587 ; 130.416,-42.079 131.686,-40.809 ; 131.661,10.166 131.661,12.706 ; 131.661,11.436 130.391,10.166 131.661,8.896 138.011,8.896 ; 131.679,-28.717 134.219,-26.177 ; 131.679,-3.127 134.219,-0.587 ; 132.949,-28.717 135.489,-26.177 ; 132.949,-3.127 135.489,-0.587 ; 135.489,-28.717 136.759,-27.447 ; 135.489,-3.127 136.759,-1.857 ; 138.036,-38.269 131.686,-38.269 130.416,-39.539 127.876,-42.079 ; 70.719,-43.227 70.719,13.923 ; 98.659,-39.417 98.659,10.113 ; 94.849,-27.447 96.119,-26.177 94.849,-27.447 ; 94.849,-1.857 96.119,-0.587 94.849,-1.857 ; 99.929,-28.717 102.469,-26.177 99.929,-28.717 ; 99.929,-3.127 102.469,-0.587 99.929,-3.127 ; 105.009,-28.717 107.549,-26.177 105.009,-28.717 ; 105.009,-3.127 107.549,-0.587 105.009,-3.127 ; 111.359,-28.717 113.899,-26.177 111.359,-28.717 ; 111.359,-3.127 113.899,-0.587 111.359,-3.127 ; 117.709,-28.717 120.249,-26.177 117.709,-28.717 ; 117.709,-3.127 120.249,-0.587 117.709,-3.127 ; 121.519,-28.717 124.059,-26.177 121.519,-28.717 ; 121.519,-3.127 124.059,-0.587 121.519,-3.127 ; 122.789,-28.717 125.329,-26.177 122.789,-28.717 ; 122.789,-3.127 125.329,-0.587 122.789,-3.127 ; 126.599,-28.717 129.139,-26.177 126.599,-28.717 ; 126.599,-3.127 129.139,-0.587 126.599,-3.127 ; 127.869,-28.717 130.409,-26.177 127.869,-28.717 ; 127.869,-3.127 130.409,-0.587 127.869,-3.127
  text "Board name: Orchard Bootcamp EVT1b" at 83.119,27.953 h1
  text "Contact: bunnie@kosagi.com" at 83.119,25.413 h1
  text "Silk: white" at 108.86,18.006 h0.76
  text "Soldermask: matte black" at 108.735,16.506 h0.76
  text "Material and thickness" at 68.179,16.463 h1.27
  text "Impedance control" at 139.754,16.413 h1.27
  text "Finish: Immersion gold" at 108.735,15.156 h0.76
  text "Plate 0.5 oz" at 83.419,11.383 h0.76
  text "Top-bottom pair" at 98.659,11.383 h0.76 r45
  text "Copper 0.5 oz" at 83.419,10.113 h0.76
  text "0.125mm = 50 ohm +/- 10%" at 139.281,8.896 h0.76
  text "Total 1.0 oz" at 83.419,8.589 h0.76
  text "Core" at 73.259,1.953 h0.76
  text "FR-4 0.125mm" at 83.419,1.953 h0.76
  text "Copper 1 oz" at 83.419,-1.857 h0.76
  text "Plane" at 140.569,-1.857 h0.76
  text "0.035mm" at 86.467,-3.127 h0.76
  text "Core" at 73.259,-15.287 h0.76
  text "FR-4 height as needed to meet overall height spec" at 83.419,-15.287 h0.76
  text "Overall height: 1.6mm +/-10%" at 69.449,-20.367 h0.76 r90
  text "Copper 1 oz" at 83.419,-27.447 h0.76
  text "0.035mm" at 86.467,-28.717 h0.76
  text "Plane" at 140.569,-28.717 h0.76
  text "Core" at 73.259,-32.527 h0.76
  text "FR-4 0.125mm" at 83.419,-32.527 h0.76
  text "Diff pairs also mirror top side impedance traits" at 139.085,-36.217 h0.76
  text "0.125mm = 50 ohm +/- 10%" at 139.052,-38.269 h0.76
  text "Copper 0.5 oz" at 83.419,-40.687 h0.76
  text "Finish: Immersion gold" at 108.81,-41.594 h0.76
  text "Plate 0.5 oz" at 83.419,-41.957 h0.76
  text "Soldermask: matte black" at 108.685,-43.194 h0.76
  text "Total 1.0oz" at 83.578,-43.525 h0.76
  text "Silk: white" at 108.81,-44.794 h0.76
  text "Mech via: 0.25mm hole / 0.5mm pad smallest" at 83.269,-46.907 h0.76
  text "Route: 0.125mm / 0.125mm smallest" at 83.269,-49.447 h0.76
Mechanical 4:
  drawing of 228 lines, arcs and shapes, not listed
